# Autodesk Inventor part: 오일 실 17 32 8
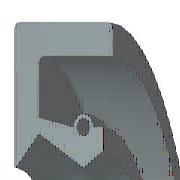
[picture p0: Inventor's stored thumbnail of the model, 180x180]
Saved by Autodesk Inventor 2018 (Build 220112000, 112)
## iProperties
IsCustomPart: 1
Created: 2012-02
Part Number: 오일 실 17 32 8
Material: 고무
Description: 오일-실
Document SubType Name: Modeling
Standard: KS B 2804
Designer: mduedu
Standards Organization: KS
Language: ko-KR
Size Designation: D - 17 32 8
Categories: <MemberInstance><Categories><Category DisplayName="샤프트 부품" InternalName="7f7aeb1f-a693-4053-b835-cee3144e0d98" Mnemonic="SHFT"><Category DisplayName="실링" Intern
Density: 0.93 g/cm^3
Appearance: 고무 - 검은색 - 버전 1.1
Author: mduedu
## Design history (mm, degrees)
revolve "본체" stored, may be unused: angle "d17" = 90 deg
revolve "스프링1" stored, may be unused: angle "d18" = 90 deg
body "Solid1"
sketch "스케치1"
  geometry: L1 (0, 16)-(8, 16); L2 (8, 14.25)-(1.75, 14.25); L3 (1.75, 10.25)-(4.9, 8.5); L4 (4.9, 8.5)-(0, 8.5); L5 (0, 0)-(9.586, 0) reference; L6 (4.9, 8.5)-(6.3, 9.375); L7 (0, 18)-(0, -3) reference; L8 (-1.941, 0)-(11.507, 0) reference; L9 (4.2, 10.6)-(1.75, 11.21); L10 (1.75, 11.21)-(1.75, 14.25); L11 (0, 16)-(0, 8.588); L12 (4.9, 8.5)-(0, 8.5); L13 (1.75, 10.25)-(0.152, 8.528); L14 (8, 16)-(8, 14.25); L15 (5.6, 10.6)-(6.3, 10.6); L16 (6.3, 10.6)-(6.3, 9.375); C1 r 0.455 at (4.9, 10.6); A1 r 0.7 centre (4.9, 10.6) between (5.6, 10.6) and (4.2, 10.6); A2 r 0.088 centre (0.088, 8.588) between (0, 8.588) and (0.152, 8.528); 1 further point
  constraints: 28 end point, 5 horizontal alignment, 5 point on line, 4 point on circle, 4 vertical alignment, 3 centre point, 3 tangent, 2 collinear, 2 horizontal, 2 perpendicular, 1 coincident, 1 parallel
  dimensions: "d0" = 32 diameter of L1 L5 (= SD2); "d1" = 1.75 distance of L1.end L2.start (= SD); "d2" = 0.91 diameter of C1 (= SPDI); "d3" = 1.4 diameter of A1 (= SPDA); "d4" = 17 diameter of L3.end L5 (= NND); "d5" = 20.5 diameter of L3.start L5 (= TKDM); "d7" = 22.42 diameter of L9.end L5 (= TKDM + 0.24 x SWDT); "d8" = 1.75 distance between parallel lines of L11 L10 (= SD); "d9" = 4.9 distance from line of L11 C1.centre (= SPDST); "d10" = 21.2 diameter of C1.centre L5 (= HLDM); "d11" = 0.0875 radius of A2 (= 0.25 x LAB); "d12" = 6.3 distance between parallel lines of L11 L16 (= SDI); "d13" = 18.75 diameter of L6.end L5 (= ABDM); "d14" = 8 distance from line of L11 L1.end (= SWDT)
fillet "모깎기1" dims "d6" = 0.3 (= RR)
other parameters: "SD2" = 32 [user parameter; used in 1 equation term], "SWDT" = 8 [user parameter; used in 2 equation terms], "RR" = 0.3 [user parameter; used in 1 equation term], "SD" = 1.75 [user parameter; used in 2 equation terms], "NND" = 17 [user parameter; used in 1 equation term], "SPDA" = 1.4 [user parameter; used in 1 equation term], "SPDI" = 0.91 [user parameter; used in 1 equation term], "TKDM" = 20.5 [user parameter; used in 2 equation terms], "HLDM" = 21.2 [user parameter; used in 1 equation term], "ABDM" = 18.75 [user parameter; used in 1 equation term], "SDI" = 6.3 [user parameter; used in 1 equation term], "SPDST" = 4.9 [user parameter; used in 1 equation term], "LAB" = 0.35 [user parameter; used in 1 equation term], "d15" = 0, "d16" = 0, "d19" = 0
